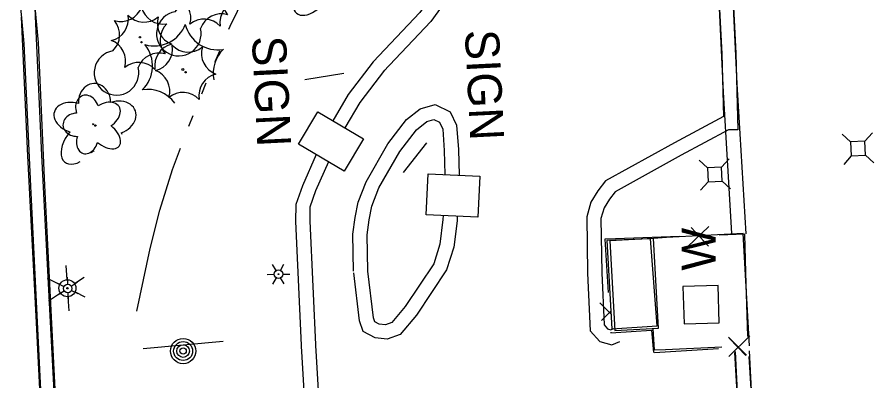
# Model space of a CAD drawing. Extents: x 588843 to 2552415, y 180129 to 269402.
# Drawn here: x 594859.2 to 595010.4, y 184706 to 184770.3 of the extents above; entities that cross this region are included whole.
import ezdxf

# ---------------------------------------------------------------- set-up
doc = ezdxf.new("R2010")
doc.units = 0
for name, color, linetype in [('Default', 7, 'Continuous'), ('E_BLD', 7, 'Continuous'), ('E_BLD_HvyDash', 7, 'Continuous'), ('E_DWY', 7, 'Continuous'), ('E_FEN_P', 7, 'Continuous'), ('E_LAND_Vegetation', 7, 'Continuous'), ('E_LTG', 7, 'Continuous'), ('E_MISCPROP', 7, 'Continuous'), ('E_SGN', 7, 'Continuous'), ('E_SGN_Text', 7, 'Continuous'), ('E_UTL_AG_Bold', 7, 'Continuous'), ('E_WTR_P', 7, 'Continuous'), ('Level 12', 7, 'Continuous'), ('Level 15', 7, 'Continuous'), ('Level 17', 7, 'Continuous')]:
    doc.layers.add(name, color=color, linetype=linetype)

# ---------------------------------------------------------------- blocks, each defined once
blk = doc.blocks.new('CTRE')
at = {"layer": 'Default'}
blk.add_circle((0, 0), 0.223, dxfattribs=at)
for centre, start, end in [((-11.97, 8.96), 280.2067, 5.9716), ((1.81, 14.92), 220.2113, 305.9762), ((13.83, 5.89), 160.2113, 245.9762), ((-13.83, -5.9), 340.2113, 65.9762), ((12.03, -9.04), 185.9272, 100.2511), ((-1.81, -14.93), 40.2113, 125.9762)]:
    blk.add_arc(centre, 7.87, start, end, dxfattribs=at)
blk = doc.blocks.new('LPOL_4')
at = {"layer": 'E_LTG'}
for p, q in [((-2.46, 4.26), (-6.56, 11.36)), ((2.46, 4.26), (6.56, 11.36)), ((-13.12, 0), (-4.92, 0)), ((4.92, 0), (13.12, 0)), ((-6.56, -11.36), (-2.46, -4.26)), ((6.56, -11.36), (2.46, -4.26))]:
    blk.add_line(p, q, dxfattribs=at)
for radius in [4.92, 4.92, 4.92, 0.41]:
    blk.add_circle((0, 0), radius, dxfattribs=at)
blk = doc.blocks.new('PED_3')
at = {"layer": 'E_UTL_AG_Bold'}
for p, q in [((-8.2, 8.2), (-17.48, 17.48)), ((8.2, 8.2), (17.48, 17.48)), ((-8.2, -8.2), (-17.48, -17.48)), ((8.2, -8.2), (17.48, -17.48))]:
    blk.add_line(p, q, dxfattribs=at)
blk.add_lwpolyline([(-8.2, -8.2), (8.2, -8.2), (8.2, 8.2), (-8.2, 8.2)], close=True, dxfattribs=at)
blk = doc.blocks.new('SIGN_3')
at = {"layer": 'E_SGN'}
blk.add_text('SIGN', height=39.37, dxfattribs=at).set_placement((-56.13, -19.68))
blk = doc.blocks.new('POLE_3')
at = {"layer": 'E_MISCPROP'}
for radius in [14.64, 10.98, 7.32, 3.66]:
    blk.add_circle((0, 0), radius, dxfattribs=at)
blk = doc.blocks.new('CTRE_4')
at = {"layer": 'E_LAND_Vegetation'}
blk.add_circle((0, 0), 0.733, dxfattribs=at)
for centre, radius, start, end in [((-39.28, 29.41), 25.81, 280.2067, 5.97162), ((5.93, 48.96), 25.81, 220.21132, 305.97623), ((45.37, 19.34), 25.81, 160.21133, 245.97624), ((-45.37, -19.35), 25.81, 340.21132, 65.97623), ((39.47, -29.65), 25.83, 100.25111, 185.92721), ((-5.93, -48.97), 25.81, 40.21133, 125.97624)]:
    blk.add_arc(centre, radius, start, end, dxfattribs=at)
blk = doc.blocks.new('DTRE_4')
at = {"layer": 'E_LAND_Vegetation'}
blk.add_circle((-0.6, 0), 0.601, dxfattribs=at)
for centre, major_axis, ratio in [((-6.14, 17.45), (4.46, -16.34), 0.782863), ((13.31, 8.98), (-17.3, -9.61), 0.691916), ((-19.26, 0.5), (16.18, -0.4), 0.832022), ((11.62, -12.16), (-16.44, 15.03), 0.560249), ((-8.18, -17.2), (5.91, 15.93), 0.716896)]:
    blk.add_ellipse(centre, major_axis=major_axis, ratio=ratio, start_param=1.570796, end_param=4.712389, dxfattribs=at)

msp = doc.modelspace()

# ---------------------------------------------------------------- linework, layer by layer
at = {"layer": 'E_BLD'}
for points in [[(594963.3, 184730.78), (594964.17, 184715.2), (594972.15, 184715.69), (594971.02, 184731.08)], [(594976.72, 184722.64), (594976.91, 184716.06), (594983.14, 184716.24), (594982.95, 184722.82)]]:
    msp.add_lwpolyline(points, close=True, dxfattribs=at)
at = {"layer": 'E_BLD_HvyDash'}
for points in [[(594908.88, 184747.82), (594912.25, 184753.51), (594920.31, 184748.74), (594916.94, 184743.05)], [(594931.42, 184735.32), (594931.77, 184742.58), (594940.85, 184742.15), (594940.5, 184734.89)]]:
    msp.add_lwpolyline(points, close=True, dxfattribs=at)
at = {"layer": 'E_DWY'}
for points in [[(594982.45, 184831.36), (594984.39, 184796.61), (594986.08, 184763.88), (594986.41, 184750.37), (594984.76, 184750.33), (594976.41, 184745.86)], [(594979.96, 184831.23), (594981.89, 184796.48), (594983.58, 184763.78), (594983.85, 184752.68), (594975.23, 184748.06)], [(594935.1, 184826.35), (594936.75, 184808.4), (594937.43, 184786.97), (594937.31, 184782.15), (594937.08, 184779.29), (594936.07, 184776.19), (594934.68, 184772.91), (594932.21, 184769.49), (594923.87, 184760.67)], [(594932.99, 184822.03), (594934.26, 184808.25), (594934.92, 184786.96), (594934.81, 184782.28), (594934.61, 184779.78), (594933.73, 184777.06), (594932.48, 184774.14), (594930.28, 184771.09), (594922.05, 184762.38)], [(594867.43, 184624.04), (594866.42, 184645.27), (594865.12, 184666.12), (594863.38, 184704.42), (594861.58, 184740.36), (594860.43, 184765.62), (594859.18, 184779.06)], [(594860.4, 184779.16), (594861.52, 184779.15), (594861.86, 184779.18), (594862.1, 184778.9), (594862.39, 184770.36), (594863.5, 184745.87), (594864.98, 184717.52), (594866.34, 184690.62)], [(594869.93, 184624.16), (594868.92, 184645.4), (594867.62, 184666.25), (594865.87, 184704.54), (594864.08, 184740.48), (594862.93, 184765.79), (594861.65, 184779.57)], [(594859.89, 184770.26), (594861.01, 184745.75), (594862.48, 184717.39), (594863.84, 184690.49)], [(594922.05, 184762.38), (594917.63, 184756.59), (594914.89, 184751.95)], [(594924.04, 184760.87), (594919.71, 184755.19), (594917.04, 184750.67)], [(594918.59, 184725.34), (594918.47, 184731.91), (594918.86, 184734.85), (594919.4, 184737.55), (594920.78, 184741.16), (594924.64, 184747.89), (594927.89, 184752.15), (594930.36, 184754.06), (594932.97, 184754.83), (594935.61, 184753.53), (594936.77, 184751.14), (594937.07, 184746.84), (594937.2, 184742.32)], [(594921.09, 184725.39), (594920.97, 184731.77), (594921.33, 184734.44), (594921.81, 184736.86), (594923.05, 184740.09), (594926.73, 184746.51), (594929.68, 184750.37), (594931.52, 184751.79), (594932.75, 184752.16), (594933.73, 184751.67), (594934.31, 184750.48), (594934.57, 184746.72), (594934.7, 184742.44)], [(594975.2, 184748.04), (594963.07, 184741.31), (594961.69, 184739.54), (594960.48, 184737.56), (594959.75, 184734.99), (594959.88, 184725.02), (594960.36, 184714.85), (594962.06, 184712.96), (594964.16, 184712.36), (594965.55, 184712.94)], [(594911.99, 184745.98), (594909.54, 184740.47), (594908.37, 184737.12), (594908.35, 184734.16), (594909.4, 184711.02)], [(594976.42, 184745.86), (594964.73, 184739.37), (594963.75, 184738.11), (594962.79, 184736.54), (594962.25, 184734.65), (594962.38, 184725.09), (594962.81, 184715.86), (594963.43, 184715.17), (594964, 184715), (594964.53, 184715.22)], [(594914.15, 184744.7), (594911.87, 184739.55), (594910.87, 184736.69), (594910.85, 184734.2), (594911.9, 184711.14)], [(594936.88, 184735.07), (594936.84, 184734.28), (594936.27, 184729.61), (594935, 184725.58), (594929.7, 184717.6), (594926.82, 184714.15), (594924.51, 184713.35), (594922.37, 184713.57), (594920.24, 184714.72), (594919.65, 184716.58), (594918.61, 184725.09)], [(594934.38, 184735.18), (594934.35, 184734.5), (594933.82, 184730.14), (594932.72, 184726.67), (594927.69, 184719.1), (594925.35, 184716.29), (594924.21, 184715.9), (594923.12, 184716), (594922.32, 184716.44), (594922.1, 184717.11), (594921.09, 184725.39)], [(594909.4, 184711.15), (594910.76, 184688.21), (594912.06, 184660.91), (594912.29, 184652.75)], [(594911.89, 184711.29), (594913.26, 184688.34), (594914.56, 184661), (594914.78, 184652.82)], [(594985.94, 184711.17), (594987.84, 184672.73), (594989.92, 184635.28), (594991.5, 184601.52), (594991.47, 184596.74), (594990.88, 184594.12), (594989.82, 184592.32), (594988.34, 184590.7), (594986.83, 184589.87), (594984.9, 184589.22), (594984, 184589.19)], [(594988.43, 184711.29), (594990.34, 184672.86), (594992.42, 184635.4), (594994, 184601.57), (594993.97, 184596.46), (594993.24, 184593.19), (594991.84, 184590.82), (594989.91, 184588.71), (594987.84, 184587.57), (594985.35, 184586.74), (594984.11, 184586.69)]]:
    msp.add_lwpolyline(points, dxfattribs=at)
at = {"layer": 'E_FEN_P'}
for p, q in [((594981.31, 184733.25), (594977.5, 184729.68)), ((594981.25, 184729.81), (594978.17, 184733.07)), ((594962.06, 184719.76), (594964.03, 184717.77)), ((594964, 184718.3), (594962.33, 184716.62)), ((594984.79, 184713.69), (594987.96, 184710.53)), ((594984.83, 184710.26), (594988.54, 184713.93))]:
    msp.add_line(p, q, dxfattribs=at)
for points in [[(594976.11, 184731.48), (594964.8, 184731.09)], [(594987.85, 184725.12), (594987.66, 184731.89), (594983.11, 184731.73)], [(594964.8, 184731.09), (594962.94, 184731.02), (594963.53, 184721.6)], [(594988.18, 184713.82), (594987.85, 184725.12)], [(594963.97, 184714.61), (594963.98, 184714.45), (594971.14, 184714.96), (594971.54, 184711)], [(594971.7, 184711.01), (594982.99, 184711.73)]]:
    msp.add_lwpolyline(points, dxfattribs=at)
at = {"layer": 'E_LAND_Vegetation'}
for centre, radius in [((594888.44, 184761), 0.167), ((594873, 184751.1), 0.128)]:
    msp.add_circle(centre, radius, dxfattribs=at)
for centre, radius, start, end in [((594883.38, 184771.07), 5.9, 253.7755, 339.5404), ((594894.59, 184770.38), 5.9, 193.7708, 279.5358), ((594877.19, 184761.65), 5.9, 313.7755, 39.5404), ((594899.7, 184760.34), 5.9, 133.7755, 191.214), ((594882.24, 184751.57), 5.91, 36.2405, 99.4914)]:
    msp.add_arc(centre, radius, start, end, dxfattribs=at)
for centre, major_axis, ratio, start_param, end_param in [((594911.49, 184774.64), (2.98, 3.7), 0.560249, 1.570796, 4.712389), ((594872.86, 184755.08), (0.13, -3.45), 0.832022, 1.570796, 4.712389), ((594876.64, 184752.51), (-3.42, -1.17), 0.782863, 1.570796, 4.712389), ((594869.23, 184752.49), (3.47, -1.05), 0.716896, 1.570796, 4.712389), ((594870.57, 184748.34), (2.98, 3.7), 0.560249, 1.570796, 4.035393), ((594875.09, 184748.26), (-2.28, 3.56), 0.691916, 4.626798, 4.712389), ((594870.57, 184748.34), (2.98, 3.7), 0.560249, 4.604289, 4.712389), ((594875.09, 184748.26), (-2.28, 3.56), 0.691916, 1.570796, 1.614495)]:
    msp.add_ellipse(centre, major_axis=major_axis, ratio=ratio, start_param=start_param, end_param=end_param, dxfattribs=at)
at = {"layer": 'E_LTG'}
for p, q in [((594867.81, 184726.35), (594867.97, 184723.85)), ((594864.48, 184724.14), (594866.72, 184723.02)), ((594869.31, 184723.19), (594871, 184724.31)), ((594864.73, 184720.14), (594866.81, 184721.53)), ((594869.4, 184721.69), (594871.11, 184720.84)), ((594868.15, 184720.86), (594868.31, 184718.36))]:
    msp.add_line(p, q, dxfattribs=at)
for radius in [1.5, 0.125]:
    msp.add_circle((594868.06, 184722.36), radius, dxfattribs=at)
at = {"layer": 'E_SGN'}
for p, q in [((594916.87, 184760.32), (594909.99, 184759.16)), ((594931.43, 184748.06), (594927.36, 184742.78)), ((594881.46, 184711.73), (594895.55, 184713.02))]:
    msp.add_line(p, q, dxfattribs=at)
at = {"layer": 'E_WTR_P'}
for points in [[(594896.57, 184768.13), (594896.79, 184768.66), (594900.73, 184776.82), (594902.63, 184779.43), (594905.29, 184782.51), (594909.73, 184785.83), (594912.39, 184788.51), (594913.88, 184789.69), (594915.3, 184790.66)], [(594894.16, 184762.43), (594894.97, 184764.33)], [(594891.76, 184756.73), (594892.56, 184758.63)], [(594889.5, 184750.97), (594890.23, 184752.9)], [(594880.31, 184718.27), (594882.68, 184729.35), (594884.39, 184736.14), (594886.63, 184743.36), (594888.04, 184747.11)]]:
    msp.add_lwpolyline(points, dxfattribs=at)
at = {"layer": 'Level 12'}
msp.add_lwpolyline([(594971.55, 184731.16), (594963.84, 184730.74), (594964.71, 184714.89), (594972.42, 184715.32), (594971.55, 184731.16)], dxfattribs=at)
at = {"layer": 'Level 15'}
msp.add_line((594984.87, 184713.53), (594987.8, 184710.49), dxfattribs=at)
for points in [[(594988.44, 184712.19), (594987.34, 184732.03), (594973.81, 184731.29)], [(594973.81, 184731.29), (594971.55, 184731.16)], [(594971.38, 184715.26), (594971.64, 184711.44)], [(594973.66, 184711.53), (594983.61, 184711.98)], [(594971.64, 184711.44), (594973.66, 184711.53)]]:
    msp.add_lwpolyline(points, dxfattribs=at)
at = {"layer": 'Level 17'}
for points in [[(594983.34, 184812.67), (594984.31, 184796.3), (594985.42, 184775.83), (594986.22, 184758.46), (594987.8, 184731.94)], [(594980.92, 184811.23), (594981.89, 184794.85), (594983, 184774.38), (594983.8, 184757.01), (594985.29, 184732)], [(594985.81, 184711.02), (594986.83, 184693.76), (594987.94, 184673.3), (594988.74, 184655.93), (594989.15, 184649.05)], [(594988.36, 184710.27), (594989.33, 184693.9), (594990.43, 184673.43), (594991.24, 184656.06), (594991.66, 184649.05)]]:
    msp.add_lwpolyline(points, dxfattribs=at)

# ---------------------------------------------------------------- block references
at = {"layer": 'E_LAND_Vegetation'}
for name, p, xscale, yscale, rotation in [('CTRE', (594891.87, 184773.62), 0.49999999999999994, 0.5000000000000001, -86.43585136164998), ('CTRE_4', (594892.64, 184773.48), 0.15240030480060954, 0.15240030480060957, 3.4338469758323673), ('CTRE', (594880.86, 184766.7), 0.49999999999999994, 0.5000000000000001, -86.43585136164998), ('CTRE_4', (594881.13, 184765.82), 0.15240030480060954, 0.15240030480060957, 3.4338469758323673), ('CTRE_4', (594888.93, 184760.52), 0.15240030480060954, 0.15240030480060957, 3.4338469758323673), ('DTRE_4', (594872.68, 184751.34), 0.15240030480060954, 0.15240030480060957, 3.4338469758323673)]:
    msp.add_blockref(name, p, dxfattribs=dict(at, xscale=xscale, yscale=yscale, rotation=rotation))
at = {"layer": 'E_LTG', "xscale": 0.15240030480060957, "yscale": 0.15240030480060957}
for p, rotation in [((594905.31, 184724.83), 0.8014450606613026), ((594868.11, 184722.31), -87.12209734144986)]:
    msp.add_blockref('LPOL_4', p, dxfattribs=dict(at, rotation=rotation))
at = {"layer": 'E_MISCPROP', "xscale": 0.15240030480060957, "yscale": 0.15240030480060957, "rotation": -87.12209734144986}
msp.add_blockref('POLE_3', (594888.49, 184711.25), dxfattribs=at)
at = {"layer": 'E_SGN_Text', "xscale": 0.15240030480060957, "yscale": 0.15240030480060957, "rotation": -87.12209734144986}
for p in [(594941.63, 184759.53), (594904.04, 184758.41)]:
    msp.add_blockref('SIGN_3', p, dxfattribs=at)
at = {"layer": 'E_UTL_AG_Bold', "xscale": 0.15240030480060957, "yscale": 0.15240030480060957, "rotation": -87.12209734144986}
for p in [(595007.63, 184747.04), (594982.35, 184742.45)]:
    msp.add_blockref('PED_3', p, dxfattribs=at)

# ---------------------------------------------------------------- texts
at = {"layer": 'Level 15'}
msp.add_text('W', height=6, rotation=90, dxfattribs=at).set_placement((594982.47, 184725.46))

doc.saveas('drawing.dxf')
